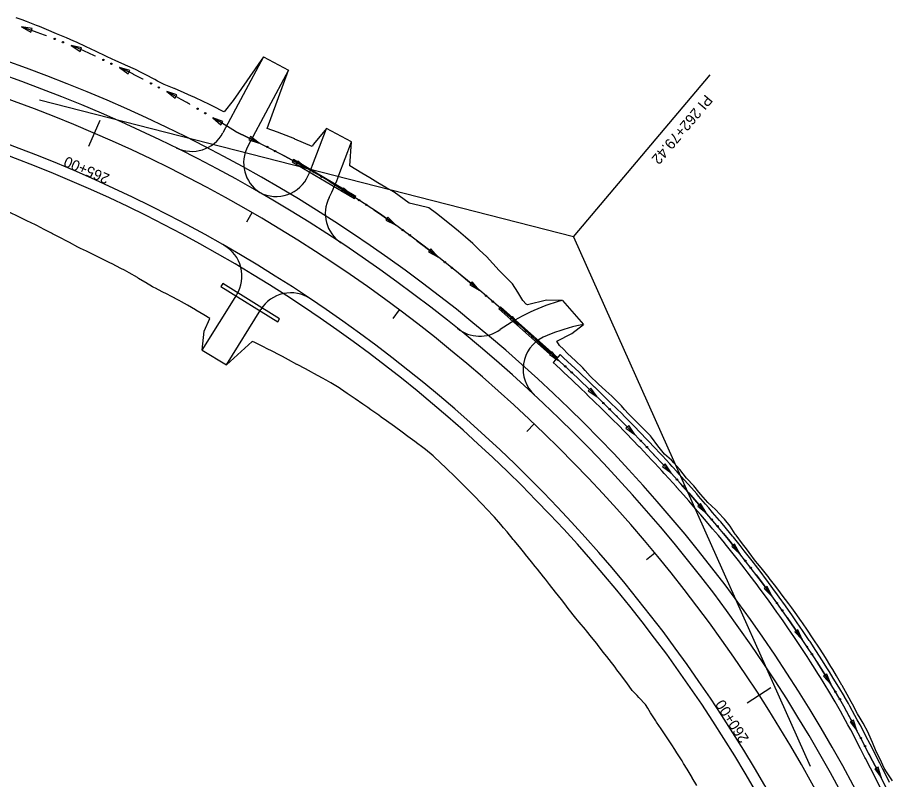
# Model space of a CAD drawing. Extents: x 948761 to 996004, y 1858548 to 1925175.
# Drawn here: x 964276 to 964776, y 1900357 to 1900788 of the extents above; entities that cross this region are included whole.
import ezdxf

# ---------------------------------------------------------------- set-up
doc = ezdxf.new("R2010")
doc.units = 0
for name, color, linetype in [('62', 7, 'Continuous'), ('R_Drainage', 7, 'Continuous'), ('R_Horz Alg', 7, 'Continuous'), ('R_Horz Alg Annot', 7, 'Continuous'), ('R_Proposed Const Limits', 7, 'Continuous'), ('R_Proposed Road', 7, 'Continuous')]:
    doc.layers.add(name, color=color, linetype=linetype)

msp = doc.modelspace()

# ---------------------------------------------------------------- linework, layer by layer
at = {"layer": '62'}
for p, q in [((964278.2, 1900783.3), (964283.5, 1900780.3)), ((964284.21, 1900782.29), (964278.2, 1900783.3)), ((964283.5, 1900780.3), (964284.21, 1900782.29)), ((964306.33, 1900772.76), (964311.4, 1900769.39)), ((964312.25, 1900771.33), (964306.33, 1900772.76)), ((964311.4, 1900769.39), (964312.25, 1900771.33)), ((964333.65, 1900760.28), (964338.56, 1900756.68)), ((964339.5, 1900758.58), (964333.65, 1900760.28)), ((964338.56, 1900756.68), (964339.5, 1900758.58)), ((964360.4, 1900746.62), (964365.19, 1900742.85)), ((964366.19, 1900744.72), (964360.4, 1900746.62)), ((964365.19, 1900742.85), (964366.19, 1900744.72)), ((964386.53, 1900731.81), (964391.13, 1900727.82)), ((964392.22, 1900729.63), (964386.53, 1900731.81)), ((964391.13, 1900727.82), (964392.22, 1900729.63)), ((964407.93, 1900721.08), (964406.99, 1900719.19)), ((964412.83, 1900717.46), (964407.93, 1900721.08)), ((964406.99, 1900719.19), (964412.83, 1900717.46)), ((964434.63, 1900707.21), (964433.59, 1900705.36)), ((964439.33, 1900703.33), (964434.63, 1900707.21)), ((964433.59, 1900705.36), (964439.33, 1900703.33)), ((964460.57, 1900691.99), (964459.45, 1900690.19)), ((964465.1, 1900687.91), (964460.57, 1900691.99)), ((964459.45, 1900690.19), (964465.1, 1900687.91)), ((964485.7, 1900675.43), (964484.48, 1900673.7)), ((964484.48, 1900673.7), (964490, 1900671.11)), ((964490, 1900671.11), (964485.7, 1900675.43)), ((964509.9, 1900657.55), (964508.6, 1900655.88)), ((964508.6, 1900655.88), (964513.99, 1900653.03)), ((964513.99, 1900653.03), (964509.9, 1900657.55)), ((964533.42, 1900638.82), (964532.07, 1900637.19)), ((964532.07, 1900637.19), (964537.36, 1900634.17)), ((964537.36, 1900634.17), (964533.42, 1900638.82)), ((964556.28, 1900619.28), (964554.88, 1900617.7)), ((964554.88, 1900617.7), (964560.07, 1900614.51)), ((964560.07, 1900614.51), (964556.28, 1900619.28)), ((964578.62, 1900599.18), (964577.2, 1900597.61)), ((964577.2, 1900597.61), (964582.34, 1900594.35)), ((964582.34, 1900594.35), (964578.62, 1900599.18)), ((964583.18, 1900597.66), (964579.15, 1900593.22)), ((964600.56, 1900578.61), (964599.08, 1900577.09)), ((964599.08, 1900577.09), (964604.11, 1900573.66)), ((964604.11, 1900573.66), (964600.56, 1900578.61)), ((964621.99, 1900557.51), (964620.46, 1900556.05)), ((964620.46, 1900556.05), (964625.38, 1900552.45)), ((964625.38, 1900552.45), (964621.99, 1900557.51)), ((964642.66, 1900535.7), (964641.11, 1900534.26)), ((964645.98, 1900530.59), (964642.66, 1900535.7)), ((964641.11, 1900534.26), (964645.98, 1900530.59)), ((964662.67, 1900513.24), (964661.07, 1900511.86)), ((964661.07, 1900511.86), (964665.79, 1900508.01)), ((964665.79, 1900508.01), (964662.67, 1900513.24)), ((964681.98, 1900490.19), (964680.33, 1900488.87)), ((964680.33, 1900488.87), (964684.91, 1900484.84)), ((964684.91, 1900484.84), (964681.98, 1900490.19)), ((964700.36, 1900466.38), (964698.65, 1900465.12)), ((964703.06, 1900460.92), (964700.36, 1900466.38)), ((964698.65, 1900465.12), (964703.06, 1900460.92)), ((964717.77, 1900441.85), (964716.02, 1900440.67)), ((964716.02, 1900440.67), (964720.25, 1900436.28)), ((964720.25, 1900436.28), (964717.77, 1900441.85)), ((964734.19, 1900416.64), (964732.39, 1900415.54)), ((964732.39, 1900415.54), (964736.42, 1900410.97)), ((964736.42, 1900410.97), (964734.19, 1900416.64)), ((964749.33, 1900390.63), (964747.45, 1900389.64)), ((964751.19, 1900384.83), (964749.33, 1900390.63)), ((964747.45, 1900389.64), (964751.19, 1900384.83)), ((964763.21, 1900363.96), (964761.32, 1900363.02)), ((964761.32, 1900363.02), (964764.93, 1900358.12)), ((964764.93, 1900358.12), (964763.21, 1900363.96))]:
    msp.add_line(p, q, dxfattribs=at)
for points in [[(964292.32, 1900778.23), (964291.23, 1900778.65), (964287.14, 1900780.12), (964285.47, 1900780.72), (964279.71, 1900782.77), (964278.2, 1900783.29)], [(964292.36, 1900778.22), (964292.32, 1900778.23)], [(964320.04, 1900766.68), (964319.46, 1900766.95), (964316.32, 1900768.38), (964313.89, 1900769.46), (964308.32, 1900771.89), (964308.31, 1900771.9), (964308.29, 1900771.91), (964306.7, 1900772.56), (964306.31, 1900772.72)], [(964320.07, 1900766.66), (964320.04, 1900766.68)], [(964347.08, 1900753.6), (964346.98, 1900753.65), (964344.68, 1900754.81), (964341.64, 1900756.34), (964341.52, 1900756.4), (964336.04, 1900759.1), (964335.29, 1900759.47), (964334.28, 1900759.96), (964333.64, 1900760.27)], [(964347.11, 1900753.58), (964347.08, 1900753.6)], [(964373.55, 1900739.4), (964372.39, 1900740.05), (964371.79, 1900740.39), (964368.54, 1900742.2), (964363.23, 1900745.1), (964363.19, 1900745.13), (964360.4, 1900746.62)], [(964373.58, 1900739.38), (964373.55, 1900739.4)], [(964399.32, 1900723.98), (964394.83, 1900726.77), (964394.39, 1900727.04), (964390.43, 1900729.47), (964389.64, 1900729.95), (964386.53, 1900731.81)], [(964767.86, 1900352.22), (964763.23, 1900361.56), (964758.44, 1900370.83), (964753.69, 1900380.12), (964748.81, 1900389.35), (964743.79, 1900398.51), (964741.55, 1900402.5), (964741.55, 1900402.51), (964738.53, 1900407.53), (964733.08, 1900416.44), (964727.5, 1900425.26), (964721.79, 1900434.01), (964715.94, 1900442.67), (964709.99, 1900451.25), (964703.93, 1900459.75), (964697.73, 1900468.16), (964691.42, 1900476.47), (964685.01, 1900484.72), (964678.49, 1900492.87), (964671.84, 1900500.92), (964665.06, 1900508.85), (964658.24, 1900516.75), (964651.36, 1900524.59), (964644.36, 1900532.32), (964637.25, 1900539.95), (964630.11, 1900547.55), (964622.88, 1900555.06), (964615.54, 1900562.47), (964608.1, 1900569.76), (964600.64, 1900577.04), (964593.15, 1900584.29), (964585.55, 1900591.42), (964577.86, 1900598.44), (964570.06, 1900605.35), (964562.38, 1900612.41), (964558.51, 1900615.89), (964554.6, 1900619.35), (964546.72, 1900626.18), (964538.8, 1900632.97), (964530.78, 1900639.64), (964522.66, 1900646.19), (964514.46, 1900652.66), (964506.22, 1900659.06), (964497.88, 1900665.35), (964489.44, 1900671.51), (964480.89, 1900677.51), (964472.2, 1900683.3), (964463.42, 1900688.96), (964454.56, 1900694.49), (964450.07, 1900697.17), (964445.56, 1900699.8), (964436.47, 1900704.95), (964427.32, 1900709.96), (964418.09, 1900714.84), (964408.74, 1900719.5), (964401.21, 1900723.09), (964399.32, 1900723.98)], [(964399.32, 1900723.98), (964401.21, 1900723.09), (964408.74, 1900719.5), (964412.83, 1900717.46)], [(964426.15, 1900710.58), (964426.19, 1900710.56)], [(964426.19, 1900710.56), (964427.32, 1900709.96), (964436.47, 1900704.95), (964439.33, 1900703.33)], [(964452.32, 1900695.83), (964452.35, 1900695.81)], [(964452.35, 1900695.81), (964454.56, 1900694.49), (964463.42, 1900688.96), (964465.09, 1900687.89)], [(964477.64, 1900679.68), (964477.67, 1900679.66)], [(964477.67, 1900679.66), (964480.89, 1900677.51), (964489.44, 1900671.51), (964489.99, 1900671.1)], [(964502.06, 1900662.19), (964502.09, 1900662.17)], [(964502.09, 1900662.17), (964506.22, 1900659.06), (964513.99, 1900653.03)], [(964525.74, 1900643.71), (964525.77, 1900643.68)], [(964525.77, 1900643.68), (964530.78, 1900639.64), (964537.36, 1900634.17)], [(964548.76, 1900624.41), (964548.79, 1900624.39)], [(964548.79, 1900624.39), (964554.6, 1900619.35), (964558.51, 1900615.89), (964560.06, 1900614.49)], [(964571.14, 1900604.39), (964571.17, 1900604.36)], [(964571.17, 1900604.36), (964577.86, 1900598.44), (964582.34, 1900594.35)], [(964769.69, 1900355.3), (964766.99, 1900360.76), (964765.9, 1900362.92), (964764.22, 1900366.22), (964761.41, 1900371.63), (964761.11, 1900372.21), (964758.65, 1900377.03), (964756.35, 1900381.49), (964755.85, 1900382.46), (964753, 1900387.87), (964751.45, 1900390.77), (964750.1, 1900393.26), (964747.16, 1900398.61), (964746.41, 1900399.97), (964744.2, 1900403.91), (964744.18, 1900403.95), (964741, 1900409.25), (964737.82, 1900414.47), (964735.63, 1900418.02), (964734.6, 1900419.67), (964731.33, 1900424.84), (964730.02, 1900426.89), (964728.02, 1900429.98), (964724.67, 1900435.09), (964724.28, 1900435.67), (964721.26, 1900440.18), (964718.42, 1900444.36), (964717.81, 1900445.24), (964714.35, 1900450.26), (964712.45, 1900452.97), (964710.83, 1900455.27), (964707.28, 1900460.24), (964706.35, 1900461.51), (964703.67, 1900465.18), (964700.14, 1900469.95), (964700.03, 1900470.1), (964696.35, 1900474.98), (964693.8, 1900478.3), (964692.63, 1900479.82), (964688.88, 1900484.65), (964687.37, 1900486.58), (964685.09, 1900489.45), (964681.26, 1900494.21), (964680.81, 1900494.76), (964677.39, 1900498.94), (964674.15, 1900502.84), (964673.47, 1900503.64), (964669.52, 1900508.31), (964667.32, 1900510.83), (964665.49, 1900512.9), (964661.55, 1900517.51), (964660.51, 1900518.72), (964657.54, 1900522.12), (964653.6, 1900526.58), (964653.49, 1900526.7), (964649.41, 1900531.24), (964646.57, 1900534.35), (964645.28, 1900535.75), (964641.13, 1900540.22), (964639.43, 1900542.01), (964636.94, 1900544.64), (964632.79, 1900549.08), (964632.28, 1900549.61), (964628.57, 1900553.5), (964625.03, 1900557.15), (964624.31, 1900557.89), (964620.03, 1900562.23), (964617.66, 1900564.59), (964615.7, 1900566.54), (964611.34, 1900570.8), (964610.18, 1900571.92), (964606.96, 1900575.01), (964602.75, 1900579.18), (964602.65, 1900579.28), (964598.28, 1900583.53), (964595.22, 1900586.46), (964593.86, 1900587.76), (964589.42, 1900591.93), (964587.59, 1900593.63), (964584.93, 1900596.07), (964583.18, 1900597.66)], [(964764.31, 1900352.65), (964761.62, 1900358.08), (964760.55, 1900360.2), (964758.88, 1900363.47), (964756.09, 1900368.85), (964755.78, 1900369.45), (964753.31, 1900374.29), (964751.02, 1900378.74), (964750.53, 1900379.68), (964747.71, 1900385.05), (964746.17, 1900387.92), (964744.83, 1900390.38), (964741.91, 1900395.71), (964741.17, 1900397.04), (964738.95, 1900401), (964735.86, 1900406.15), (964732.71, 1900411.33), (964730.53, 1900414.85), (964729.51, 1900416.48), (964726.27, 1900421.62), (964724.97, 1900423.64), (964722.99, 1900426.71), (964719.66, 1900431.79), (964719.29, 1900432.34), (964716.29, 1900436.82), (964713.47, 1900440.97), (964712.88, 1900441.83), (964709.42, 1900446.83), (964707.54, 1900449.52), (964705.94, 1900451.79), (964702.41, 1900456.73), (964701.5, 1900457.98), (964698.84, 1900461.63), (964695.33, 1900466.37), (964695.23, 1900466.5), (964691.57, 1900471.34), (964689.04, 1900474.65), (964687.88, 1900476.16), (964684.16, 1900480.95), (964682.66, 1900482.86), (964680.4, 1900485.71), (964676.6, 1900490.43), (964676.16, 1900490.97), (964672.76, 1900495.12), (964669.54, 1900498.99), (964668.88, 1900499.78), (964664.97, 1900504.4), (964662.81, 1900506.87), (964660.96, 1900508.96), (964657, 1900513.6), (964655.98, 1900514.78), (964653.03, 1900518.17), (964649.11, 1900522.6), (964649.02, 1900522.71), (964644.97, 1900527.21), (964642.15, 1900530.3), (964640.88, 1900531.68), (964636.75, 1900536.11), (964635.07, 1900537.89), (964632.58, 1900540.53), (964628.42, 1900544.96), (964627.93, 1900545.48), (964624.24, 1900549.34), (964620.73, 1900552.97), (964620.03, 1900553.68), (964615.77, 1900557.99), (964613.42, 1900560.34), (964611.49, 1900562.26), (964607.16, 1900566.5), (964606.01, 1900567.6), (964602.77, 1900570.71), (964598.53, 1900574.91), (964598.44, 1900575), (964594.11, 1900579.22), (964591.08, 1900582.12), (964589.74, 1900583.4), (964585.33, 1900587.55), (964583.52, 1900589.22), (964580.88, 1900591.65), (964579.15, 1900593.22)], [(964593.32, 1900584.13), (964593.34, 1900584.1)], [(964593.34, 1900584.1), (964600.64, 1900577.04), (964604.11, 1900573.66)], [(964614.83, 1900563.16), (964614.85, 1900563.14)], [(964614.85, 1900563.14), (964615.54, 1900562.47), (964622.88, 1900555.06), (964625.38, 1900552.45)], [(964635.72, 1900541.58), (964635.74, 1900541.56)], [(964635.74, 1900541.55), (964637.25, 1900539.95), (964644.36, 1900532.32), (964645.95, 1900530.57)], [(964655.94, 1900519.37), (964655.96, 1900519.35)], [(964655.96, 1900519.34), (964658.24, 1900516.75), (964665.06, 1900508.85), (964665.78, 1900508.01)], [(964675.45, 1900496.54), (964675.48, 1900496.51)], [(964675.48, 1900496.51), (964678.49, 1900492.87), (964684.91, 1900484.84)], [(964694.08, 1900472.97), (964694.1, 1900472.94)], [(964694.1, 1900472.94), (964697.73, 1900468.16), (964703.06, 1900460.92)], [(964711.76, 1900448.7), (964711.78, 1900448.67)], [(964711.78, 1900448.67), (964715.94, 1900442.67), (964720.25, 1900436.28)], [(964728.46, 1900423.73), (964728.48, 1900423.7)], [(964728.48, 1900423.7), (964733.08, 1900416.44), (964736.42, 1900410.97)], [(964744.04, 1900398.05), (964744.06, 1900398.02)], [(964744.06, 1900398.02), (964748.81, 1900389.35), (964751.19, 1900384.83)], [(964758.09, 1900371.51), (964758.11, 1900371.48)], [(964758.11, 1900371.48), (964758.44, 1900370.83), (964763.23, 1900361.56), (964764.93, 1900358.12)]]:
    msp.add_lwpolyline(points, dxfattribs=at)
for centre in [(964297, 1900776.41), (964301.65, 1900774.56), (964324.58, 1900764.54), (964329.11, 1900762.4), (964351.53, 1900751.27), (964355.96, 1900748.95), (964377.88, 1900736.86), (964382.21, 1900734.34), (964417.33, 1900715.26), (964421.77, 1900712.94), (964443.7, 1900700.89), (964448.04, 1900698.39), (964469.32, 1900685.2), (964473.51, 1900682.47), (964494.06, 1900668.18), (964498.1, 1900665.22), (964517.94, 1900649.96), (964521.87, 1900646.86), (964541.2, 1900630.96), (964545.01, 1900627.7), (964563.79, 1900611.16), (964567.48, 1900607.77), (964586.06, 1900591), (964589.71, 1900587.57), (964607.71, 1900570.18), (964611.29, 1900566.68), (964628.88, 1900548.87), (964632.33, 1900545.24), (964649.34, 1900526.88), (964652.68, 1900523.14), (964669.06, 1900504.22), (964672.31, 1900500.41), (964688.01, 1900480.92), (964691.09, 1900476.96), (964706.02, 1900456.88), (964708.93, 1900452.8), (964723.05, 1900432.14), (964725.79, 1900427.94), (964739.06, 1900406.72), (964741.64, 1900402.42), (964753.57, 1900380.42), (964755.85, 1900375.96)]:
    msp.add_circle(centre, 0.375, dxfattribs=at)
at = {"layer": 'R_Drainage'}
for p, q in [((964432.12, 1900708.18), (964431.35, 1900706.89)), ((964431.35, 1900706.89), (964466.68, 1900685.99)), ((964467.44, 1900687.28), (964432.12, 1900708.18)), ((964466.68, 1900685.99), (964467.44, 1900687.28)), ((964392.13, 1900637.93), (964391.08, 1900636.24)), ((964391.08, 1900636.24), (964423.24, 1900616.26)), ((964424.3, 1900617.96), (964392.13, 1900637.93)), ((964549.42, 1900624.78), (964548.42, 1900623.66)), ((964548.42, 1900623.66), (964580.67, 1900594.88)), ((964581.67, 1900596), (964549.42, 1900624.78)), ((964423.24, 1900616.26), (964424.3, 1900617.96)), ((964580.67, 1900594.88), (964581.67, 1900596))]:
    msp.add_line(p, q, dxfattribs=at)
at = {"layer": 'R_Horz Alg'}
msp.add_arc((963983.23, 1899943.63), 848.83, 24.09145, 75.65786, dxfattribs=at)
at = {"layer": 'R_Horz Alg Annot'}
for q in [(964288.34, 1900741.75), (964724.84, 1900364.54)]:
    msp.add_line((964590.74, 1900664.43), q, dxfattribs=at)
for points in [[(964590.74, 1900664.43), (964668.08, 1900756.19)], [(964316.38, 1900715.64), (964322.72, 1900730.33)], [(964405.81, 1900672.86), (964408.82, 1900678.05)], [(964488.6, 1900618.13), (964492.19, 1900622.94)], [(964564.37, 1900554.06), (964568.51, 1900558.4)], [(964632.09, 1900481.52), (964636.71, 1900485.35)], [(964689.14, 1900400.44), (964702.57, 1900409.13)]]:
    msp.add_lwpolyline(points, dxfattribs=at)
at = {"layer": 'R_Proposed Const Limits'}
for points in [[(964392.94, 1900735.18), (964392.46, 1900735.42), (964386.98, 1900738.15), (964383.88, 1900739.65), (964381.46, 1900740.81), (964375.92, 1900743.4), (964374.37, 1900744.1), (964370.33, 1900745.9), (964364.75, 1900748.31), (964364.71, 1900748.33), (964359.05, 1900750.68), (964355.17, 1900752.58), (964353.59, 1900753.46), (964348.17, 1900756.3), (964345.87, 1900757.49), (964342.71, 1900759.11), (964337.14, 1900761.64), (964336.37, 1900761.97), (964331.52, 1900764.07), (964326.78, 1900766.24), (964325.95, 1900766.62), (964320.4, 1900769.24), (964317.28, 1900770.78), (964314.88, 1900771.93), (964309.36, 1900774.54), (964309.35, 1900774.55), (964309.33, 1900774.56), (964307.75, 1900775.24), (964303.69, 1900776.98), (964298.06, 1900779.37), (964298.04, 1900779.39), (964292.38, 1900781.78), (964288.33, 1900783.38), (964286.67, 1900784.03), (964280.96, 1900786.31), (964278.54, 1900787.27), (964275.21, 1900788.47)], [(964415.28, 1900766.26), (964398.1, 1900741.62), (964392.94, 1900735.18)], [(964450.9, 1900725.78), (964443.52, 1900716.87), (964442.73, 1900715.51), (964437.87, 1900717.62), (964433.01, 1900719.73), (964432.95, 1900719.76), (964428.03, 1900721.71), (964423.07, 1900723.68), (964423.07, 1900723.68), (964417.34, 1900725.75), (964429.38, 1900758.69)], [(964584.46, 1900628.35), (964575.38, 1900628.45), (964564.63, 1900625.75), (964563.85, 1900626.2), (964562.12, 1900628.37), (964559.22, 1900633.02), (964556.27, 1900637.75), (964552.48, 1900641.49), (964548.69, 1900645.24), (964545.05, 1900649.19), (964541.4, 1900653.14), (964537.56, 1900656.87), (964533.72, 1900660.61), (964529.66, 1900664.07), (964525.6, 1900667.53), (964521.46, 1900670.89), (964513.1, 1900677.51), (964508.86, 1900680.76), (964503.27, 1900682.05), (964497.67, 1900683.34), (964489.14, 1900689.67), (964484.54, 1900692.35), (964479.95, 1900695.02), (964475.39, 1900697.75), (964470.84, 1900700.49), (964464.12, 1900704.56), (964465.11, 1900718.14)], [(964380.56, 1900600.17), (964381.69, 1900610.91), (964384.79, 1900618.13), (964381.43, 1900620.16), (964376.85, 1900622.88), (964376.8, 1900622.91), (964372.09, 1900625.56), (964368.8, 1900627.44), (964367.41, 1900628.23), (964362.67, 1900630.81), (964360.64, 1900631.79), (964357.85, 1900633.23), (964354.08, 1900635.2), (964353.07, 1900635.73), (964352.44, 1900636.05), (964348.39, 1900638.41), (964348, 1900638.65), (964344.48, 1900640.8), (964343.78, 1900641.23), (964339.1, 1900643.92), (964336.43, 1900645.38), (964334.34, 1900646.48), (964329.55, 1900648.96), (964328.21, 1900649.64), (964324.73, 1900651.39), (964319.93, 1900653.77), (964319.89, 1900653.79), (964315.03, 1900656.14), (964311.59, 1900657.81), (964310.17, 1900658.51), (964305.4, 1900661.07), (964303.39, 1900662.16), (964300.63, 1900663.64), (964295.8, 1900666.09), (964295.13, 1900666.4), (964290.97, 1900668.55), (964286.89, 1900670.73), (964286.17, 1900671.1), (964281.25, 1900673.38), (964278.49, 1900674.73), (964276.38, 1900675.78), (964271.53, 1900678.16)], [(964771.34, 1900356.24), (964767.91, 1900361.34), (964766.72, 1900363.43), (964765.15, 1900366.79), (964762.42, 1900372.26), (964762.12, 1900372.86), (964760.02, 1900377.92), (964758.05, 1900382.59), (964757.58, 1900383.57), (964754.73, 1900388.99), (964753.04, 1900391.81), (964751.58, 1900394.24), (964748.66, 1900399.62), (964747.94, 1900400.99), (964745.76, 1900405.06), (964742.84, 1900410.17), (964742.74, 1900410.35), (964739.65, 1900415.64), (964737.52, 1900419.24), (964736.53, 1900420.91), (964733.37, 1900426.17), (964732.1, 1900428.24), (964730.12, 1900431.36), (964726.48, 1900436.72), (964726.1, 1900437.28), (964723.24, 1900441.51), (964720.38, 1900445.68), (964719.77, 1900446.55), (964716.26, 1900451.58), (964714.34, 1900454.29), (964712.66, 1900456.53), (964708.9, 1900461.38), (964707.96, 1900462.64), (964705.23, 1900466.28), (964701.62, 1900471.01), (964701.51, 1900471.15), (964697.68, 1900475.93), (964695.05, 1900479.2), (964693.89, 1900480.74), (964690.2, 1900485.62), (964688.71, 1900487.57), (964686.5, 1900490.49), (964682.8, 1900495.37), (964682.36, 1900495.93), (964679.44, 1900500.52), (964676.17, 1900504.42), (964675.49, 1900505.21), (964671.28, 1900509.67), (964668.84, 1900511.98), (964666.8, 1900513.91), (964662.76, 1900518.5), (964661.7, 1900519.69), (964658.9, 1900523.25), (964654.79, 1900527.57), (964654.69, 1900527.69), (964650.97, 1900532.56), (964647.5, 1900536.39), (964646.21, 1900537.79), (964642.27, 1900541.19), (964640.71, 1900543.11), (964638.46, 1900545.99), (964634.84, 1900550.97), (964634.4, 1900551.56), (964630.66, 1900555.44), (964626.97, 1900558.97), (964626.23, 1900559.67), (964621.94, 1900564.04), (964619.71, 1900566.54), (964617.86, 1900568.6), (964613.55, 1900572.95), (964612.39, 1900574.06), (964609.06, 1900577.11), (964604.68, 1900581.18), (964604.58, 1900581.27), (964600.11, 1900585.45), (964597.34, 1900588.69), (964596.11, 1900590.12), (964591.7, 1900594.37), (964589.86, 1900596.05), (964587.19, 1900598.51), (964585.01, 1900600.66), (964582.84, 1900602.82), (964581.37, 1900605.34), (964589.75, 1900609.6), (964596.44, 1900614.68)], [(964660.59, 1900353.52), (964657.94, 1900358.03), (964657.85, 1900358.19), (964655.07, 1900362.86), (964653.12, 1900366.02), (964652.21, 1900367.49), (964649.3, 1900372.08), (964648.13, 1900373.9), (964646.35, 1900376.66), (964643.37, 1900381.21), (964643.03, 1900381.72), (964640.35, 1900385.74), (964637.83, 1900389.47), (964637.3, 1900390.24), (964634.37, 1900394.83), (964632.79, 1900397.32), (964631.44, 1900399.42), (964627.73, 1900403.47), (964626.76, 1900404.49), (964623.97, 1900407.46), (964620.91, 1900411.76), (964620.82, 1900411.89), (964617.52, 1900416.21), (964615.26, 1900419.17), (964614.25, 1900420.55), (964610.96, 1900424.88), (964609.62, 1900426.59), (964607.59, 1900429.14), (964604.29, 1900433.46), (964603.9, 1900433.95), (964600.87, 1900437.68), (964598.02, 1900441.18), (964597.45, 1900441.9), (964594.03, 1900446.12), (964592.1, 1900448.37), (964590.48, 1900450.24), (964587.22, 1900454.6), (964586.38, 1900455.73), (964583.96, 1900458.96), (964580.63, 1900463.09), (964580.54, 1900463.19), (964577.15, 1900467.46), (964574.85, 1900470.43), (964573.81, 1900471.77), (964570.42, 1900476.04), (964568.99, 1900477.71), (964566.91, 1900480.21), (964563.52, 1900484.5), (964563.12, 1900485.01), (964560.11, 1900488.77), (964557.19, 1900492.27), (964556.6, 1900492.96), (964553.11, 1900497.18), (964551.19, 1900499.49), (964549.6, 1900501.38), (964546.03, 1900505.54), (964545.05, 1900506.58), (964542.25, 1900509.48), (964538.57, 1900513.36), (964538.49, 1900513.45), (964534.7, 1900517.4), (964532.06, 1900520.12), (964530.88, 1900521.32), (964527.02, 1900525.2), (964525.42, 1900526.75), (964523.09, 1900529), (964519.14, 1900532.79), (964518.66, 1900533.26), (964515.2, 1900536.59), (964511.88, 1900539.76), (964511.24, 1900540.37), (964506.99, 1900543.83), (964504.6, 1900545.69), (964502.63, 1900547.16), (964500.82, 1900548.48), (964498.2, 1900550.38), (964497.01, 1900551.24), (964493.8, 1900553.65), (964489.48, 1900556.84), (964489.39, 1900556.9), (964484.93, 1900560.07), (964481.83, 1900562.28), (964480.49, 1900563.26), (964476.05, 1900566.45), (964474.21, 1900567.73), (964471.55, 1900569.54), (964467.03, 1900572.61), (964466.46, 1900573), (964462.52, 1900575.7), (964458.72, 1900578.26), (964458, 1900578.74), (964453.37, 1900581.65), (964450.7, 1900583.12), (964448.56, 1900584.29), (964443.76, 1900586.93), (964442.46, 1900587.64), (964438.95, 1900589.54), (964434.21, 1900592.09), (964434.14, 1900592.13), (964429.33, 1900594.71), (964425.98, 1900596.54), (964424.54, 1900597.32), (964419.69, 1900599.81), (964417.66, 1900600.8), (964414.78, 1900602.2), (964409.91, 1900604.63), (964409.28, 1900604.93), (964408.83, 1900605.13), (964394.29, 1900591.94)]]:
    msp.add_lwpolyline(points, dxfattribs=at)
at = {"layer": 'R_Proposed Road'}
for p, q in [((964415.28, 1900766.26), (964392.23, 1900723.28)), ((964415.28, 1900766.26), (964429.38, 1900758.69)), ((964429.38, 1900758.69), (964406.33, 1900715.71)), ((964442.98, 1900704.96), (964450.9, 1900725.78)), ((964465.11, 1900718.14), (964450.9, 1900725.78)), ((964457.93, 1900699.27), (964465.11, 1900718.14)), ((964380.56, 1900600.17), (964400.03, 1900631.59)), ((964584.46, 1900628.35), (964596.44, 1900614.68)), ((964394.29, 1900591.94), (964413.64, 1900623.17)), ((964596.44, 1900614.68), (964592.69, 1900613.87)), ((964380.56, 1900600.17), (964394.29, 1900591.94))]:
    msp.add_line(p, q, dxfattribs=at)
for centre, radius, start, end in [((963983.23, 1899943.63), 868.83, 24.09145, 75.65786), ((963983.23, 1899943.63), 860.83, 24.09145, 75.65786), ((963983.23, 1899943.63), 824.83, 24.09145, 75.65786), ((963983.23, 1899943.63), 818.83, 24.09145, 75.65786), ((964374.6, 1900732.73), 20, 243.6194, 331.7978), ((964423.96, 1900706.26), 20, 151.7978, 237.2827), ((964333.62, 1900746.55), 117, 336.0809, 339.1774), ((964422.29, 1900707.22), 20, 242.7947, 336.0809), ((964333.62, 1900746.55), 133, 333.2124, 339.1774), ((964470.2, 1900677.6), 20, 153.2124, 236.4364), ((964383.03, 1900642.13), 20, 328.2203, 60.214), ((964430.64, 1900612.63), 20, 56.2266, 148.2203), ((964612.05, 1900523.93), 108, 104.7988, 125.5419), ((964537.64, 1900628.08), 20, 230.9919, 305.5419), ((964612.57, 1900522.7), 93.31, 102.2986, 114.7622), ((964582.21, 1900589.44), 20, 115.8846, 227.154)]:
    msp.add_arc(centre, radius, start, end, dxfattribs=at)

# ---------------------------------------------------------------- texts
at = {"layer": 'R_Horz Alg Annot'}
for s, rotation, p in [('PI 262+79.42', 229.8747, (964665.46, 1900745.32)), ('265+00', 156.6578, (964328.62, 1900699.46)), ('260+00', 122.9078, (964690.33, 1900380.19))]:
    msp.add_text(s, height=6, rotation=rotation, dxfattribs=at).set_placement(p)

doc.saveas('drawing.dxf')
